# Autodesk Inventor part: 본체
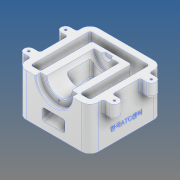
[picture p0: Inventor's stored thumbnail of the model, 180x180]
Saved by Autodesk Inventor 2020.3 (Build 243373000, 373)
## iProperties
Created: 2022-03
Part Number: 본체
Material: 알루미늄 6061
Document SubType Name: Modeling
Designer: EZDESIGN
Density: 2.7 g/cm^3
Appearance: 알루미늄 - 평지
Mass: 1023.99 g
Surface Area: 845.338 cm^2
Volume: 379.256 cm^3
Author: EZDESIGN
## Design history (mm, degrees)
sketch "스케치1"
  geometry: L1 (55, 55)-(-55, 55); L2 (-55, 55)-(-55, -55); L3 (-55, -55)-(55, -55); L4 (55, -55)-(55, 55); L5 (55, 55)-(-55, -55); L6 (-55, 55)-(55, -55); 1 further point
  constraints: 12 end point, 2 midpoint, 2 parallel, 1 horizontal, 1 perpendicular
  dimensions: "d0" = 110 distance of L3.end L2.end; "d1" = 110 distance of L2.end L1.end
extrude "돌출1" new body sketch "스케치1" distance "d2" = 65; taper "d3" = 0 deg
fillet "모깎기1" dims "d4" = 13
sketch "스케치2"
  geometry: L1 (-45, 45)-(-45, -45); L2 (-45, -45)-(-30, -45); L3 (-30, -45)-(-30, 33); L4 (-30, 33)-(30, 33); L5 (30, 33)-(30, -45); L6 (30, -45)-(45, -45); L7 (45, -45)-(45, 45); L8 (45, 45)-(-45, 45); L9 (42, 55)-(-42, 55) reference; L10 (-55, 42)-(-55, -42) reference; L11 (-42, -55)-(42, -55) reference; L12 (55, -42)-(55, 42) reference; A1 r 13 centre (42, 42) between (55, 42) and (42, 55) reference; A2 r 13 centre (-42, 42) between (-42, 55) and (-55, 42) reference; A3 r 13 centre (-42, -42) between (-55, -42) and (-42, -55) reference; A4 r 13 centre (42, -42) between (42, -55) and (55, -42) reference; 1 further point
  constraints: 16 end point, 6 perpendicular, 2 point on line, 1 vertical
  dimensions: "d5" = 10 distance between parallel lines of L8 L9; "d6" = 10 distance between parallel lines of L12 L7; "d7" = 10 distance between parallel lines of L10 L1; "d8" = 10 distance between parallel lines of L11 L2; "d9" = 60 distance of L3.end L4.end; "d10" = 30 distance from line of point (0, 0) L5; "d11" = 22 distance between parallel lines of L4 L9
extrude "돌출2" cut sketch "스케치2" distance "d12" = 65; taper "d13" = 0 deg
sketch "스케치3"
  geometry: L1 (14, 65)-(70, 65); L2 (0, 0)-(84, 0) reference; L3 (0, 65)-(84, 65) reference; A1 r 28 centre (42, 65) between (14, 65) and (70, 65); 3 further points
  constraints: 2 end point, 2 midpoint, 2 point on circle, 1 centre point, 1 collinear, 1 horizontal, 1 horizontal alignment, 1 vertical alignment
  dimensions: "d14" = 56 diameter of A1
extrude "돌출3" cut sketch "스케치3" distance "d15" = 8; taper "d16" = 0 deg
sketch "스케치4"
  geometry: L1 (14, 65)-(70, 65) reference; L2 (23, 65)-(61, 65); A1 r 28 centre (42, 65) between (14, 65) and (70, 65) reference; A2 r 19 centre (42, 65) between (23, 65) and (61, 65); 1 further point
  constraints: 2 end point, 2 point on circle, 2 point on line, 1 centre point, 1 coincident
  dimensions: "d17" = 38 diameter of A2
extrude "돌출4" cut sketch "스케치4" distance "d18" = 72; taper "d19" = 0 deg
sketch "스케치5"
  geometry: L1 (23, 65)-(61, 65) reference; C1 r 7.5 at (42, 65); A1 r 19 centre (42, 65) between (23, 65) and (61, 65) reference; 1 further point
  constraints: 1 centre point, 1 coincident
  dimensions: "d20" = 15 diameter of C1
extrude "돌출5" cut sketch "스케치5" distance "d21" = 4; taper "d22" = -30 deg
sketch "스케치6" dims "d23" = 46
  geometry: L1 (14, 65)-(23, 65) reference; L2 (61, 65)-(70, 65) reference; A1 r 19 centre (42, 65) between (23, 65) and (61, 65) reference; A2 r 28 centre (42, 65) between (14, 65) and (70, 65) reference; 3 further points
  constraints: 2 vertical alignment, 1 coincident, 2 other
hole "구멍1" sketch "스케치6" at (42, 42) diameter "d24" = 3.242; stored, may be unused: countersink angle "d28" = 90 deg, drill point angle "d30" = 118 deg; dims "d25" = 9, "d26" = 4, "d27" = 2, "d29" = 11
sketch "스케치8"
  geometry: L1 (78, 0)-(0, 0) reference; L2 (78, 0)-(78, -65) reference; L3 (0, -65)-(78, -65) reference; L4 (0, 0)-(0, -65) reference; L5 (0, -65)-(78, -65); L6 (78, -35)-(0, -55.9); L7 (0, -65)-(0, -55.9); L8 (78, -35)-(78, -65); 1 further point
  constraints: 8 end point, 2 collinear, 2 point on line, 1 vertical
  dimensions: "d32" = 30 distance of L2.end L6.start; "d33" = 75 deg angle of L6 L2
extrude "돌출6" cut sketch "스케치8" distance "d34" = 60; taper "d35" = 0 deg
sketch "스케치9"
  geometry: L1 (29.197, 55)-(11.597, 55); L2 (11.597, 55)-(31.425, -19); L3 (31.425, -19)-(74.362, -19); L4 (74.362, -19)-(74.362, 19); L5 (74.362, 19)-(38.843, 19); L6 (38.843, 19)-(29.197, 55); L7 (0, 55)-(65, 55) reference; L8 (30, -33)-(9.1, 45) reference; 1 further point
  constraints: 12 end point, 3 parallel, 2 perpendicular, 1 collinear, 1 horizontal
  dimensions: "d37" = 17 distance between parallel lines of L2 L6; "d38" = 38 distance between parallel lines of L3 L5; "d39" = 36 distance between parallel lines of L5 L7; "d40" = 5 distance between parallel lines of L8 L2; "d41" = 42.93694 distance from line of L2.end L4
extrude "돌출7" cut sketch "스케치9" stored distance "d42" = 34; taper "d43" = 0 deg
sketch "스케치10"
  geometry: L1 (54, 28)-(65, 28); L2 (54, 21)-(65, 21); L3 (65, 35)-(54, 35); L4 (55, -42)-(55, 42) reference; L5 (42, 55)-(-42, 55) reference; A1 r 7 centre (54, 28) between (54, 35) and (54, 21); A2 r 7 centre (65, 28) between (65, 21) and (65, 35); 4 further points
  constraints: 8 end point, 4 point on circle, 4 tangent, 2 centre point, 1 horizontal, 1 midpoint, 1 parallel
  dimensions: "d44" = 14 diameter of A2; "d45" = 27 vertical distance of point (59.5, 28) L5.start; "d46" = 10 horizontal distance of L1.end L4.end; "d47" = 1 distance from line of L4 L3.end
extrude "돌출8" join sketch "스케치10" distance "d48" = 20; taper "d49" = 0 deg
sketch "스케치11"
  geometry: A1 r 7 centre (65, 28) between (65, 21) and (65, 35) reference; 3 further points
  constraints: 1 coincident
hole "구멍2" sketch "스케치11" at (65, 28), (82.881, 81.093) diameter "d50" = 3.242; stored, may be unused: countersink angle "d54" = 90 deg, drill point angle "d56" = 118 deg; dims "d51" = 9, "d52" = 4, "d53" = 2, "d55" = 11
fillet "모깎기2" dims "d57" = 1
fillet "모깎기3" dims "d58" = 3
fillet "모깎기4" dims "d59" = 3
fillet "모깎기5" dims "d60" = 3
fillet "모깎기6" dims "d61" = 3
fillet "모깎기7" dims "d62" = 3
fillet "모깎기8" dims "d63" = 3
fillet "모깎기9" dims "d64" = 3
fillet "모깎기10" dims "d65" = 3
node "작업 평면1"
sketch "스케치12"
  geometry: L1 (-13, 65)-(-13, 0) reference; 2 further points
  constraints: 1 other
  dimensions: "d67" = 20 distance of point (42, 0) point (42, 20); "d68" = 55 distance from line of point (42, 20) L1
feature "엠보싱1" sketch "스케치12" dims "d0" = 110, "d1" = 110, "d69" = 0.5, "d70" = 0
chamfer "모따기1" distance "d71" = 1; stored, may be unused: second distance "d72" = 2, angle "d73" = 45 deg
node "솔리드1"
mirror "미러1"
mirror "미러2"
node "투영된 루프1"
node "투영된 루프2"
node "투영된 루프3"
node "투영된 루프4"
node "투영된 루프6"
feature "A9D066F2-1C7D-4E18-AEED-F7BC21143FA4" dims "d50" = 3.242, "d51" = 9, "d52" = 4, "d53" = 2, "d54" = 90 deg, "d55" = 11, "d56" = 118 deg
other parameters: "d66" = 5
